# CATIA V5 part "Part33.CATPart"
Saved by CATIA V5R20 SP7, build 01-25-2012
Part number: corps vérin gauche
Bounding box of the stored display mesh (mm): x -22.68 to 6.616, y -59 to -0.033, z 41.393 to 52.425
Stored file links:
  F:\Travaux\Modélisations\CFAO_2011\CFAO_2011_MMS\CFAO_2011_MMS_DONE\CFAO_2011_MMS_jboiteux\Catia\Part33.CATPart
  U:\finthinkmotion\stepper.CATProduct
  F:\Travaux\Modélisations\CFAO_2011\CFAO_2011_MMS\CFAO_2011_MMS_DONE\CFAO_2011_MMS_jboiteux\Catia\bati.CATPart
  F:\Travaux\Modélisations\CFAO_2011\CFAO_2011_MMS\CFAO_2011_MMS_DONE\CFAO_2011_MMS_jboiteux\Catia\Part1.CATPart
  F:\Travaux\Modélisations\CFAO_2011\CFAO_2011_MMS\CFAO_2011_MMS_DONE\CFAO_2011_MMS_jboiteux\Catia\part4.CATPart
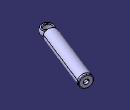
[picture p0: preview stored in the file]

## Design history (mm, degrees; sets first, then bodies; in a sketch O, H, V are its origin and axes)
Parameters
  rayontube = 9 mm {= External.royontubebati}
  longueurpied = 108 mm {= External.longueurpied}
External parameters (linked from other documents)
  External.royontubebati = 9 mm
  External.longueurpied = 108 mm
Sketch1 on Plane2, origin (39.4626, -76.1315, 27.3092), H (0.9095, -0.3384, 0.2416), V (-0.2182, 0.1063, 0.9701)
  circle A1 centre (-54.5636, 34.5073) radius 4.95
  point P1 (-54.5636, 34.5073)
  reference projected point E1 (-54.5636, 34.5073) from Line1
  distance E1 P1 = 0
  radius A1 = 4.95 {= rayontube *1.1/2}
Set1
  Plane1: linked copy from another document
  Point1: linked copy from another document
  Plane2: linked copy from another document
  Line1: linked copy from another document
Body1 (main body)
  Plane3: type Offset, RefPlane Plane1, Offset 2 {= rayontube /4.5}
  Plane4: type Offset, RefPlane Plane1, Offset 2 {= rayontube /4.5}, reversed
  Sketch2 on Plane1, origin (0, 0, 47.6), H (1, 0, 0), V (0, -1, 0)
    arc A1 centre (-17.69, 54) radius 4 from (-17.69, 50) to (-17.69, 58) ccw
    point P1 (-17.69, 54)
    reference projected point E1 (-17.69, 54) from Point1
    arc A2 centre (-17.69, 54) radius 5 from (-17.69, 49) to (-17.69, 59) ccw
    line L1 (-17.69, 49) -> (-17.69, 50)
    reference projected point E2 (-17.69, 54) from Point1
    line L2 (-17.69, 58) -> (-17.69, 59)
    radius A1 = 4 {= rayontube *2/3/2+1mm}
    radius A2 = 5 {= rayontube *2/2/3+2mm}
    coincidence: E1 P1, E2 L1, L1 L2
    vertical: L1 V, L2 V
  Shaft1: profile Sketch2, axis Sketch2.L1, angle 360
  Split1: SplitPlane Plane4
  Split2: SplitPlane Plane3
  Pad1: profile Sketch1, direction (-0.354, -0.935, 0.0228), length -4.0909 {= -rayontube /2.2}, opposite side length 54 {= longueurpied/2}
  Fillet1: radius 1 {= rayontube /9}, on edge [face of Pad1 from Sketch1.A1 | end face of Pad1]
  Sketch3 on start face of Pad1, origin (64.1339, -27.7735, 24.9668), H (-0.9095, 0.3384, -0.2416), V (-0.2182, 0.1063, 0.9701)
    circle A1 centre (60.0708, 37.0236) radius 3.95
    reference projected circle E1 centre (60.0708, 37.0236) radius 4.95 from edge [start face of Pad1 | face of Pad1 from Sketch1.A1]
    radius A1 = 3.95 {= rayontube *79/180}
    concentricity: E1 A1
  Pocket1: profile Sketch3, direction (-0.354, -0.935, 0.0228), length 48.5 {= longueurpied /2-rayontube /2-1mm}
  Sketch4 on start face of Pad1, origin (64.1339, -27.7735, 24.9668), H (-0.9095, 0.3384, -0.2416), V (-0.2182, 0.1063, 0.9701)
    projected circle E1 centre (60.0708, 37.0236) radius 4.95 from edge [start face of Pad1 | face of Pad1 from Sketch1.A1]
    circle A1 centre (60.0708, 37.0236) radius 1.8
    point P1 (60.0708, 37.0236)
    reference projected point E2 (60.0708, 37.0236) from Line1
    distance E2 P1 = 0
    radius A1 = 1.8 {= rayontube *0.4/2}
  Pad2: profile Sketch4, direction (0.354, 0.935, -0.0228), length 2
  Fillet2: radius 0.5 {= rayontube /18}, on edge [face of Pad2 from Sketch4.E1 | end face of Pad2]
